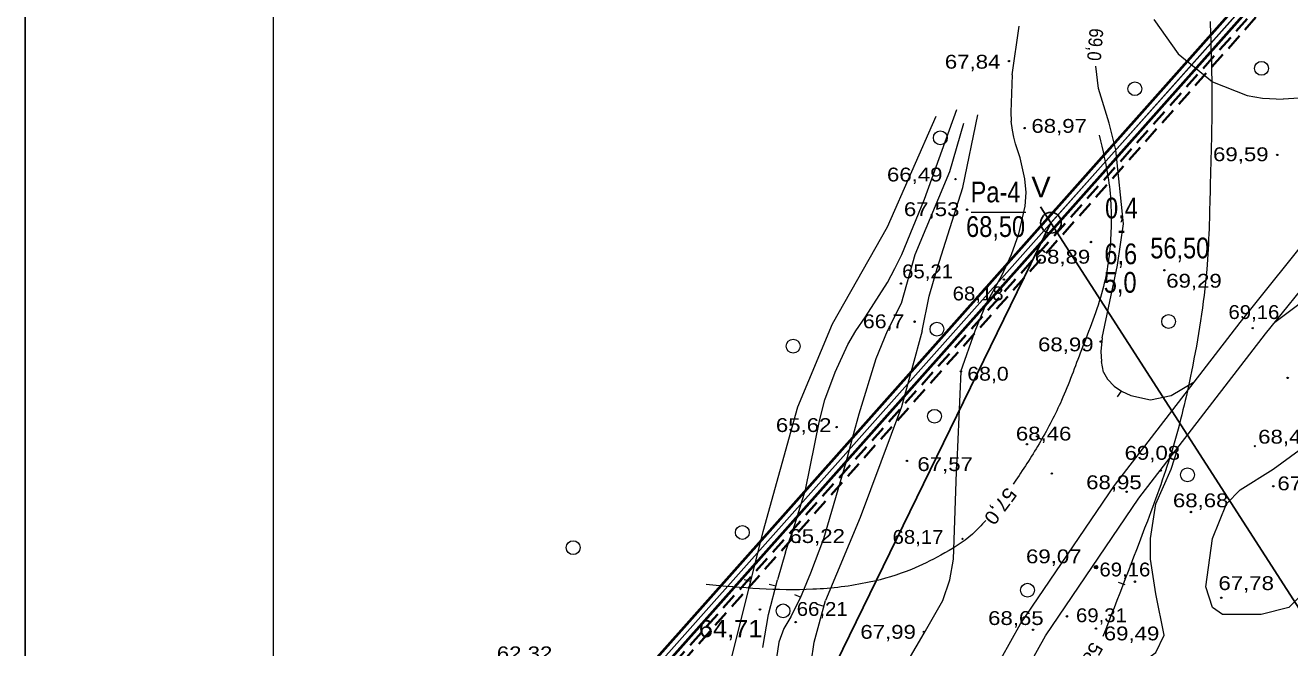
# Model space of a CAD drawing. Extents: x 628176 to 629009, y 6439913 to 6440496.
# Drawn here: x 628178.3 to 628361.2, y 6440262.2 to 6440352.1 of the extents above; entities that cross this region are included whole.
import ezdxf
from ezdxf.enums import TextEntityAlignment as Align

# ---------------------------------------------------------------- set-up
doc = ezdxf.new("R2010")
doc.units = 0
doc.header["$LTSCALE"] = 0.8
doc.header["$PDMODE"] = 32
doc.header["$PDSIZE"] = 0.4
doc.linetypes.add('MEDIUM_DASHED', pattern=[4.5, 3, -1.5])
for name, color, linetype, lineweight in [('1', 7, 'Continuous', 13), ('11', 7, 'Continuous', 13), ('12', 7, 'Continuous', 13), ('14', 7, 'Continuous', 25), ('16', 7, 'Continuous', 13), ('20', 7, 'Continuous', 40), ('21', 7, 'MEDIUM_DASHED', 35), ('3', 7, 'Continuous', 13), ('50', 7, 'Continuous', 13)]:
    doc.layers.add(name, color=color, linetype=linetype, lineweight=lineweight)

msp = doc.modelspace()

# ---------------------------------------------------------------- hatches: boundary and pattern name
at = {"layer": '1'}
for points in [[(628320.635, 6440346.9743, 1), (628320.435, 6440346.9743, 1)], [(628322.9002, 6440337.2961, 1), (628322.7002, 6440337.2961, 1)], [(628359.4511, 6440333.412, 1), (628359.2511, 6440333.412, 1)], [(628312.9125, 6440329.9235, 1), (628312.7125, 6440329.9235, 1)], [(628314.5901, 6440325.503, 1), (628314.3901, 6440325.503, 1)], [(628332.5061, 6440320.8301, 1), (628332.3061, 6440320.8301, 1)], [(628343.1221, 6440316.7483, 1), (628342.9221, 6440316.7483, 1)], [(628305.0093, 6440314.82, 1), (628304.8093, 6440314.82, 1)], [(628319.9222, 6440315.4068, 1), (628319.7222, 6440315.4068, 1)], [(628306.9995, 6440309.3151, 1), (628306.7995, 6440309.3151, 1)], [(628355.9088, 6440308.3796, 1), (628355.7088, 6440308.3796, 1)], [(628333.9269, 6440306.4327, 1), (628333.7269, 6440306.4327, 1)], [(628313.699, 6440302.1196, 1), (628313.499, 6440302.1196, 1)], [(628360.9518, 6440301.1816, 1), (628360.7518, 6440301.1816, 1)], [(628295.7095, 6440294.0865, 1), (628295.5095, 6440294.0865, 1)], [(628323.2439, 6440291.6128, 1), (628323.0439, 6440291.6128, 1)], [(628356.2049, 6440291.3263, 1), (628356.0049, 6440291.3263, 1)], [(628305.8831, 6440289.1894, 1), (628305.6831, 6440289.1894, 1)], [(628326.8438, 6440287.3609, 1), (628326.6438, 6440287.3609, 1)], [(628342.5977, 6440287.7968, 1), (628342.3977, 6440287.7968, 1)], [(628337.6639, 6440284.7326, 1), (628337.4639, 6440284.7326, 1)], [(628358.8808, 6440285.5294, 1), (628358.6808, 6440285.5294, 1)], [(628346.9527, 6440281.8109, 1), (628346.7527, 6440281.8109, 1)], [(628290.2356, 6440277.4586, 1), (628290.0356, 6440277.4586, 1)], [(628313.924, 6440277.9326, 1), (628313.724, 6440277.9326, 1)], [(628333.3856, 6440273.832, 1), (628332.8856, 6440273.832, 1)], [(628333.2356, 6440273.832, 1), (628333.0356, 6440273.832, 1)], [(628338.8681, 6440271.7421, 1), (628338.6681, 6440271.7421, 1)], [(628351.3443, 6440269.4165, 1), (628351.1443, 6440269.4165, 1)], [(628284.6389, 6440267.7248, 1), (628284.4389, 6440267.7248, 1)], [(628329.0205, 6440266.7325, 1), (628328.8205, 6440266.7325, 1)], [(628289.7918, 6440265.9094, 1), (628289.5918, 6440265.9094, 1)], [(628324.1373, 6440264.797, 1), (628323.9373, 6440264.797, 1)], [(628333.2122, 6440264.964, 1), (628333.0122, 6440264.964, 1)], [(628308.3527, 6440264.4754, 1), (628308.1527, 6440264.4754, 1)]]:
    msp.add_hatch(color=256, dxfattribs=at).paths.add_polyline_path(points)

# ---------------------------------------------------------------- linework, layer by layer
for p, q in [((628353.99, 6440309.2), (628372.24, 6440332)), ((628357.63, 6440307.56), (628375.42, 6440329.58)), ((628335.79, 6440285.66), (628353.99, 6440309.2)), ((628339.34, 6440283.81), (628357.63, 6440307.56)), ((628322.23, 6440265.66), (628335.79, 6440285.66)), ((628325.84, 6440263.93), (628339.34, 6440283.81)), ((628308.95, 6440241.98), (628322.23, 6440265.66)), ((628312.42, 6440240), (628325.84, 6440263.93))]:
    msp.add_line(p, q, dxfattribs=at)
for centre, radius in [((628320.535, 6440346.9743), 0.1), ((628357.0739, 6440345.9265), 1), ((628338.7604, 6440342.9806), 1), ((628310.6162, 6440335.8833), 1), ((628322.8002, 6440337.2961), 0.1), ((628359.3511, 6440333.412), 0.1), ((628312.8125, 6440329.9235), 0.1), ((628314.4901, 6440325.503), 0.1), ((628332.4061, 6440320.8301), 0.1), ((628343.0221, 6440316.7483), 0.1), ((628304.9093, 6440314.82), 0.1), ((628319.8222, 6440315.4068), 0.1), ((628306.8995, 6440309.3151), 0.1), ((628310.1267, 6440308.2286), 1), ((628343.6323, 6440309.3354), 1), ((628289.3245, 6440305.7813), 1), ((628355.8088, 6440308.3796), 0.1), ((628333.8269, 6440306.4327), 0.1), ((628313.599, 6440302.1196), 0.1), ((628360.8518, 6440301.1816), 0.1), ((628309.7792, 6440295.6448), 1), ((628295.6095, 6440294.0865), 0.1), ((628323.1439, 6440291.6128), 0.1), ((628356.1049, 6440291.3263), 0.1), ((628305.7831, 6440289.1894), 0.1), ((628326.7438, 6440287.3609), 0.1), ((628342.4977, 6440287.7968), 0.1), ((628346.3704, 6440287.1815), 1), ((628337.5639, 6440284.7326), 0.1), ((628358.7808, 6440285.5294), 0.1), ((628346.8527, 6440281.8109), 0.1), ((628281.9826, 6440278.8608), 1), ((628257.5094, 6440276.6582), 1), ((628290.1356, 6440277.4586), 0.1), ((628313.824, 6440277.9326), 0.1), ((628333.1356, 6440273.832), 0.25), ((628333.1356, 6440273.832), 0.1), ((628323.2209, 6440270.5039), 1), ((628338.7681, 6440271.7421), 0.1), ((628287.8743, 6440267.5169), 1), ((628351.2443, 6440269.4165), 0.1), ((628284.5389, 6440267.7248), 0.1), ((628328.9205, 6440266.7325), 0.1), ((628289.6918, 6440265.9094), 0.1), ((628324.0373, 6440264.797), 0.1), ((628333.1122, 6440264.964), 0.1), ((628308.2527, 6440264.4754), 0.1)]:
    msp.add_circle(centre, radius, dxfattribs=at)
at = {"layer": '11'}
msp.add_lwpolyline([(628497.5, 6440118.54), (628474.19, 6440080.39), (628272.25, 6440200.89), (628236.02, 6440221.83), (628393.19, 6440398.39)], dxfattribs=at)
msp.add_point((628333.14, 6440273.83), dxfattribs=at)
at = {"layer": '12'}
msp.add_line((628315.08, 6440325.16), (628322.99, 6440325.16), dxfattribs=at)
at = {"layer": '12', "lineweight": 25}
msp.add_circle((628326.6164, 6440323.6021), 1.5, dxfattribs=at)
at = {"layer": '14'}
for p, q in [((628393.19, 6440398.39), (628326.62, 6440323.6)), ((628326.62, 6440323.6), (628325.1, 6440325.89)), ((628326.62, 6440323.6), (628267.86, 6440203.3))]:
    msp.add_line(p, q, dxfattribs=at)
msp.add_lwpolyline([(628326.62, 6440323.6), (628400.29, 6440209.22), (628472.21, 6440157.1), (628497.5, 6440118.54), (628498.85, 6440116.47)], dxfattribs=at)
at = {"layer": '16'}
for p, q in [((628324.42, 6440292.83), (628325.28, 6440292.31)), ((628336.35, 6440271.67), (628337.29, 6440271.33))]:
    msp.add_line(p, q, dxfattribs=at)
for points in [[(628349.64, 6440352.69), (628349.89, 6440342.62), (628349.64, 6440328.63), (628349.15, 6440316.85), (628346.94, 6440302.12), (628344.24, 6440291.07), (628340.56, 6440280.51), (628334.13, 6440263.82)], [(628333.58, 6440336.27), (628334.94, 6440329.83), (628335.27, 6440321.86), (628334.09, 6440313.89), (628331.03, 6440305.24), (628328.15, 6440297.94), (628325.1, 6440292.01), (628321.54, 6440286.41), (628321.13, 6440285.81)], [(628317.18, 6440280.6), (628315.26, 6440278.61), (628310.68, 6440275.56), (628306.44, 6440273.52), (628300.34, 6440271.66), (628292.2, 6440270.64), (628276.77, 6440271.32)]]:
    msp.add_spline(points, degree=3, dxfattribs=at)
at = {"layer": '20'}
msp.add_line((628235.32, 6440222.24), (628409.42, 6440417.82), dxfattribs=at)
at = {"layer": '21', "linetype": 'Continuous', "lineweight": 40}
msp.add_lwpolyline([(628320.39, 6440173.09), (628272.66, 6440201.58), (628237.27, 6440222.03), (628393.6, 6440397.65)], dxfattribs=at)
at = {"layer": '21'}
for points in [[(628321.72, 6440173.24), (628273.06, 6440202.27), (628238.52, 6440222.23), (628394.01, 6440396.91)], [(628321.66, 6440174.2), (628273.47, 6440202.96), (628239.77, 6440222.44), (628394.43, 6440396.17)]]:
    msp.add_lwpolyline(points, dxfattribs=at)
at = {"layer": '3'}
for p, q in [((628321, 6440345), (628322, 6440352)), ((628333.51, 6440343), (628333.11, 6440346.22)), ((628321, 6440345), (628320.8, 6440339.61)), ((628357.21, 6440341.63), (628360.22, 6440341.49)), ((628364, 6440341.72), (628360.22, 6440341.49)), ((628313.87, 6440328.73), (628316.05, 6440339.23)), ((628320.8, 6440339.61), (628320.86, 6440338.29)), ((628321.51, 6440335), (628321.24, 6440336)), ((628322.15, 6440333), (628321.51, 6440335)), ((628310.14, 6440317), (628313.87, 6440328.73)), ((628309, 6440313), (628310.14, 6440317)), ((628317.29, 6440312), (628319.52, 6440316)), ((628334.04, 6440307), (628336.22, 6440317.48)), ((628308, 6440308), (628309, 6440313)), ((628334.24, 6440302), (628333.91, 6440303.54)), ((628313.6, 6440302.12), (628313, 6440289)), ((628336.26, 6440298.46), (628336.82, 6440299.29)), ((628291.11, 6440285), (628293.14, 6440295)), ((628297, 6440289), (628298.04, 6440293)), ((628289.59, 6440280), (628291.11, 6440285)), ((628288.24, 6440276), (628289.59, 6440280)), ((628288.24, 6440276), (628287.07, 6440272)), ((628282.24, 6440272.04), (628283.21, 6440271.8)), ((628285.76, 6440267), (628287.07, 6440272)), ((628285.87, 6440271.38), (628286.84, 6440271.13)), ((628289.52, 6440269.9), (628290.44, 6440269.51)), ((628292.82, 6440268.48), (628293.78, 6440268.21)), ((628284.96, 6440262.22), (628285.76, 6440267))]:
    msp.add_line(p, q, dxfattribs=at)
for points in [[(628341.52, 6440353), (628345, 6440348), (628350, 6440344), (628355, 6440342), (628357.21, 6440341.63)], [(628336, 6440334.15), (628335.02, 6440338), (628333.51, 6440343)], [(628293.14, 6440295), (628293.92, 6440298), (628295.39, 6440302), (628297.25, 6440306), (628298.42, 6440308), (628299.79, 6440310), (628302.96, 6440315), (628304.04, 6440317), (628305.04, 6440319), (628308.31, 6440327), (628313, 6440340)], [(628285, 6440279), (628290, 6440297), (628295, 6440309), (628303, 6440323), (628310, 6440339)], [(628303, 6440308), (628305, 6440312), (628307, 6440319), (628312, 6440331), (628314, 6440338)], [(628321.24, 6440336), (628321.05, 6440337), (628320.86, 6440338.29)], [(628319.52, 6440316), (628320.89, 6440319), (628321.99, 6440322), (628322.91, 6440326), (628323.03, 6440327.99), (628322.86, 6440329.96), (628322.15, 6440333)], [(628336.22, 6440317.48), (628337.09, 6440323.46), (628336, 6440334.15)], [(628359, 6440309.25), (628364, 6440313), (628370, 6440319), (628374, 6440325)], [(628313.6, 6440302.12), (628315.64, 6440308), (628317.29, 6440312)], [(628371.31, 6440273.83), (628370, 6440276), (628369, 6440276), (628367, 6440275), (628365, 6440272), (628361, 6440268), (628357, 6440267), (628351.41, 6440267), (628350, 6440268), (628349, 6440271), (628350, 6440278), (628352, 6440283), (628354, 6440285), (628358.78, 6440288), (628367, 6440294), (628372, 6440299), (628376.27, 6440304), (628378.53, 6440307), (628381.54, 6440312)], [(628308, 6440308), (628305, 6440297), (628299, 6440281), (628294, 6440269)], [(628298.04, 6440293), (628298.88, 6440296), (628301.36, 6440304), (628303, 6440308)], [(628334.04, 6440307), (628333.83, 6440305), (628333.91, 6440303.54)], [(628334.24, 6440302), (628334.79, 6440301), (628335.77, 6440300), (628336.82, 6440299.29), (628338.18, 6440298.65), (628341, 6440298), (628344, 6440298.65), (628347.35, 6440300.62)], [(628341, 6440275), (628341, 6440278), (628341.81, 6440283), (628344, 6440288), (628344.98, 6440291)], [(628289, 6440266.65), (628290.4, 6440269.43), (628291.9, 6440273), (628293.76, 6440278), (628297, 6440289)], [(628303.32, 6440255), (628304, 6440257), (628308.28, 6440264.32), (628311, 6440269), (628312, 6440272), (628312.51, 6440275), (628313, 6440289)], [(628278.61, 6440254), (628279.52, 6440257), (628285, 6440279)], [(628338.27, 6440259), (628341.81, 6440261.52), (628343, 6440264), (628341.81, 6440270), (628341, 6440275)], [(628291.96, 6440260), (628292.36, 6440263), (628294, 6440269)], [(628289, 6440266.65), (628288, 6440265), (628287.25, 6440263), (628286.9, 6440260.74), (628287.02, 6440258.27)]]:
    msp.add_lwpolyline(points, dxfattribs=at)
at = {"layer": '50', "lineweight": 25}
msp.add_lwpolyline([(628178.27, 6440495.9), (629008.51, 6440495.9), (629008.51, 6439918.47), (628178.27, 6439918.47)], close=True, dxfattribs=at)
at = {"layer": '50'}
msp.add_lwpolyline([(628214.18, 6440472.45), (628760.23, 6440472.45), (628760.23, 6440028.67), (628214.18, 6440028.67)], close=True, dxfattribs=at)

# ---------------------------------------------------------------- texts
at = {"layer": '1'}
for s, height, width, p in [('67,84', 2, 1.2, (628311.27, 6440345.88)), ('68,97', 2, 1.2, (628323.79, 6440336.61)), ('69,59', 2, 1.2, (628350.06, 6440332.51)), ('66,49', 2, 1.2, (628302.9, 6440329.58)), ('67,53', 2, 1.2, (628305.35, 6440324.57)), ('68,89', 2, 1.2, (628324.27, 6440317.7)), ('65,21', 2, 1.1, (628305.09, 6440315.58)), ('69,29', 2, 1.2, (628343.29, 6440314.23)), ('68,18', 2, 1.1, (628312.4, 6440312.39)), ('69,16', 2, 1.1, (628352.29, 6440309.7)), ('66,7', 2, 1.15, (628299.42, 6440308.37)), ('68,99', 2, 1.2, (628324.75, 6440305.03)), ('68,0', 2, 1.15, (628314.52, 6440300.79)), ('65,62', 2, 1.2, (628286.83, 6440293.37)), ('68,46', 2, 1.2, (628321.54, 6440292.14)), ('68,46', 2, 1.2, (628356.59, 6440291.69)), ('69,08', 2, 1.2, (628337.27, 6440289.36)), ('67,57', 2, 1.2, (628307.3, 6440287.73)), ('68,95', 2, 1.2, (628331.71, 6440285.11)), ('67,74', 2, 1.2, (628359.37, 6440284.95)), ('68,68', 2, 1.2, (628344.26, 6440282.49)), ('65,22', 2, 1.2, (628288.79, 6440277.33)), ('68,17', 2, 1.1, (628303.71, 6440277.21)), ('69,07', 2, 1.2, (628323.01, 6440274.4)), ('69,16', 2, 1.1, (628333.63, 6440272.5)), ('67,78', 2, 1.2, (628350.84, 6440270.53)), ('66,21', 2, 1.1, (628289.85, 6440266.8)), ('68,65', 2, 1.2, (628317.53, 6440265.48)), ('69,31', 2, 1.1, (628330.24, 6440265.89)), ('64,71', 2.5, 1.1, (628275.69, 6440263.71)), ('67,99', 2, 1.2, (628299.05, 6440263.49)), ('69,49', 2, 1.2, (628334.26, 6440263.26)), ('62,32', 2, 1.2, (628246.47, 6440260.38))]:
    msp.add_text(s, height=height, dxfattribs=dict(at, width=width)).set_placement(p)
at = {"layer": '12', "width": 0.85}
for s, p in [('Pa-4', (628318.6, 6440326.56)), ('0,4', (628336.815, 6440324.24)), ('68,50', (628318.61, 6440321.56)), ('-', (628336.815, 6440321.14)), ('56,50', (628345.25, 6440318.46)), ('6,6', (628336.71, 6440317.62)), ('5,0', (628336.63, 6440313.5))]:
    msp.add_text(s, height=3, dxfattribs=at).set_placement(p, align=Align.CENTER)
at = {"layer": '14', "width": 1.05}
msp.add_text('V', height=3, dxfattribs=at).set_placement((628325.18, 6440327.29), align=Align.CENTER)
at = {"layer": '16'}
for s, rotation, width, p in [('57,0', 233.163, 1.1, (628318.5268, 6440283.2395)), ('58,0', 240.255, 1.05, (628331.1635, 6440260.8011))]:
    msp.add_text(s, height=2, rotation=rotation, dxfattribs=dict(at, width=width)).set_placement(p, align=Align.CENTER)
at = {"layer": '3', "width": 0.9}
msp.add_text('69,0', height=2, rotation=265.197, dxfattribs=at).set_placement((628332.22, 6440351.78))

doc.saveas('drawing.dxf')
